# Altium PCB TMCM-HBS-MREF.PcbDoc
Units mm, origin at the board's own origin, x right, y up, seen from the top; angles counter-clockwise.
Board outline 55 x 85 mm, 4 copper layers (Top Layer, Mid1, Mid2, Bottom Layer), stack 1.546 mm thick; 61 components, 40 nets, 208 pads, 113 vias.
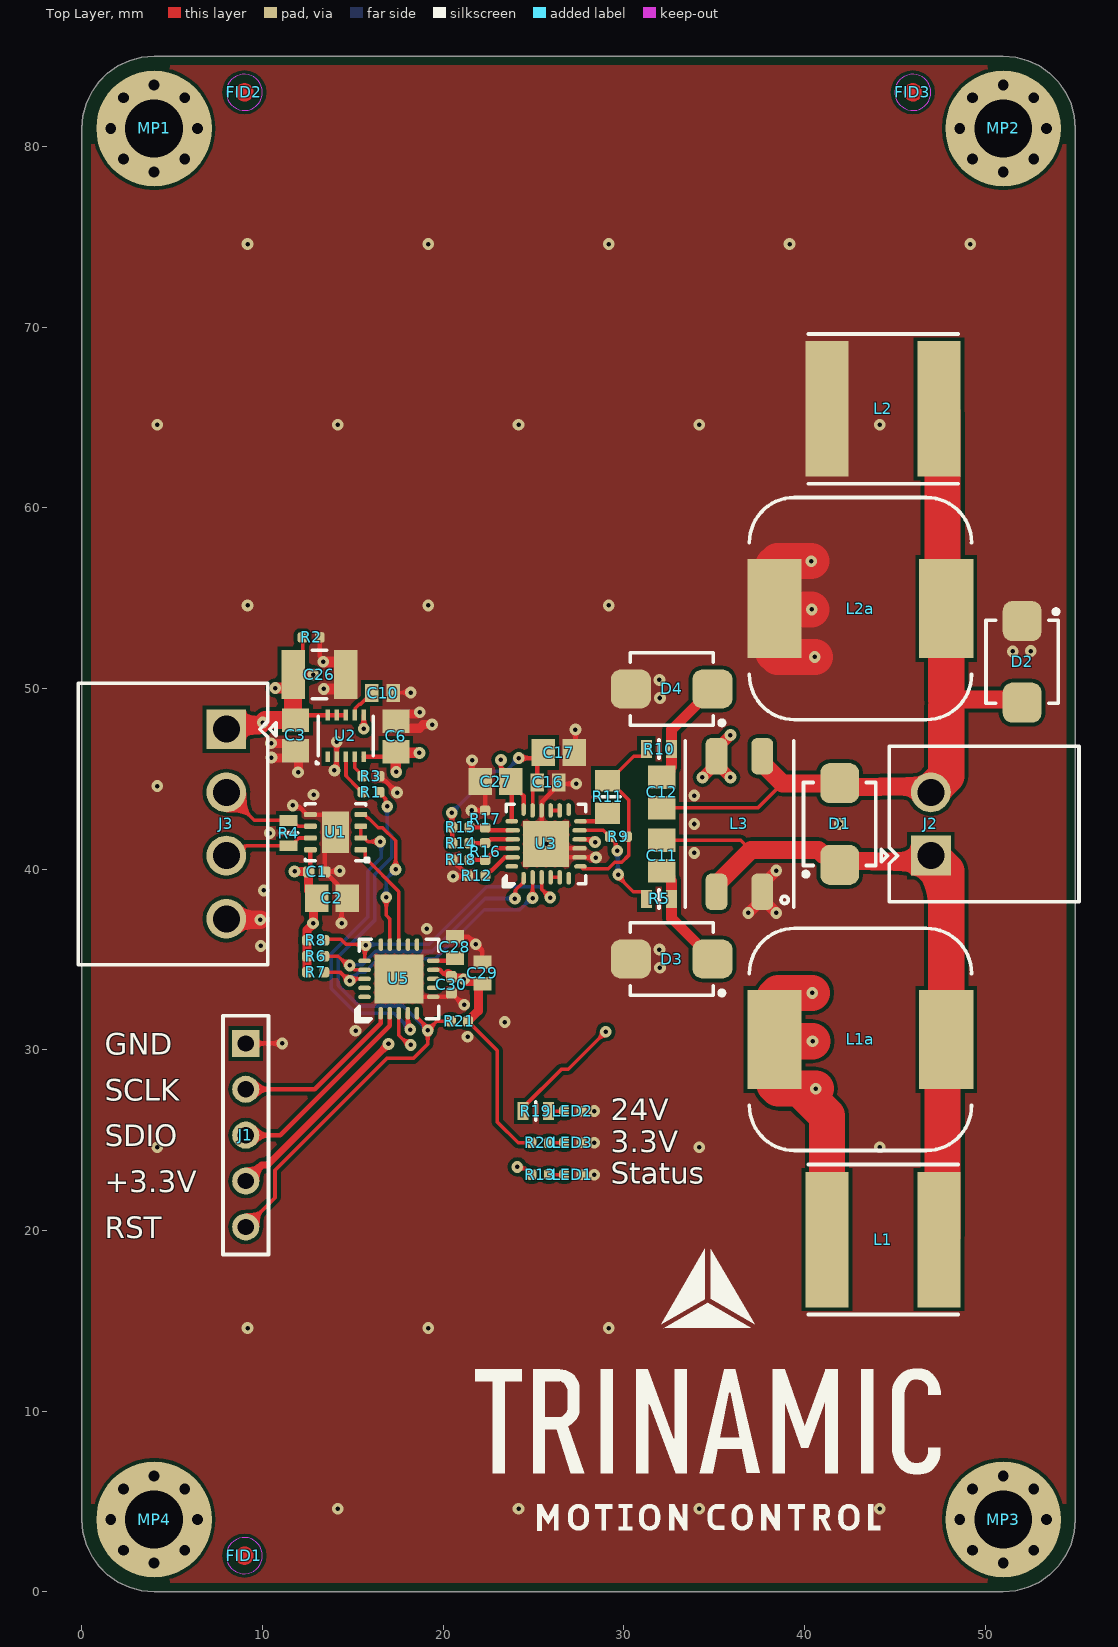
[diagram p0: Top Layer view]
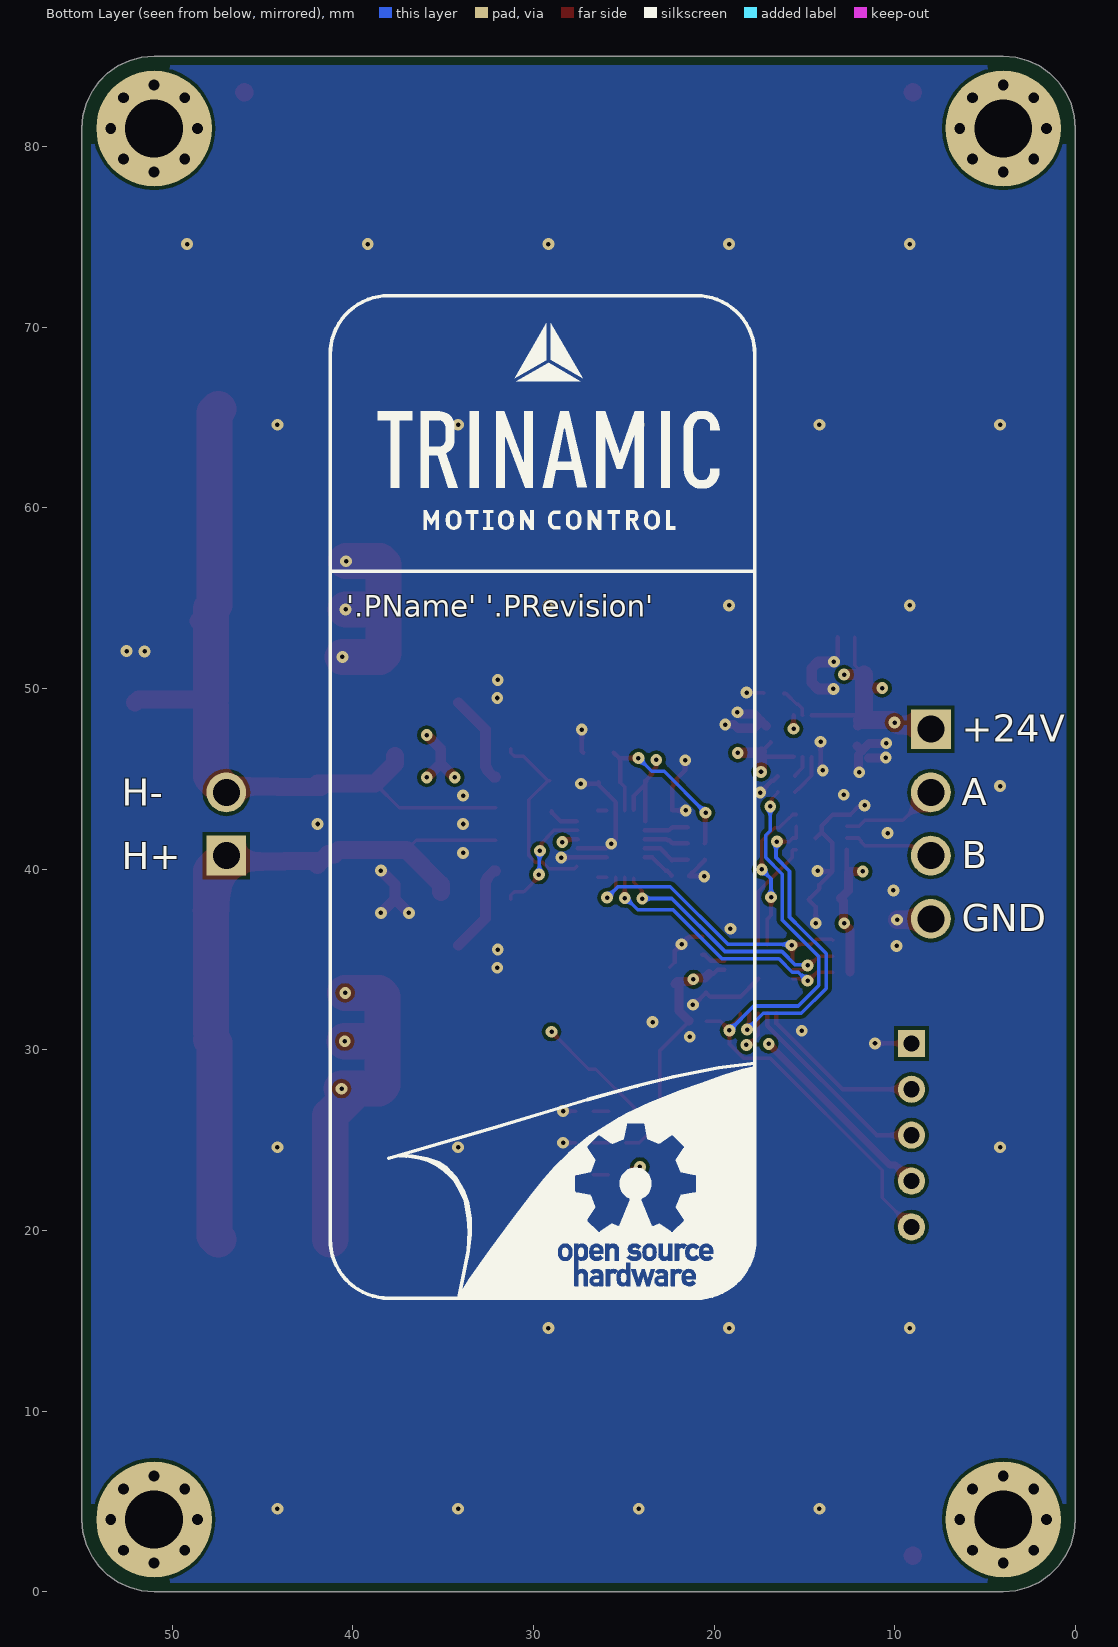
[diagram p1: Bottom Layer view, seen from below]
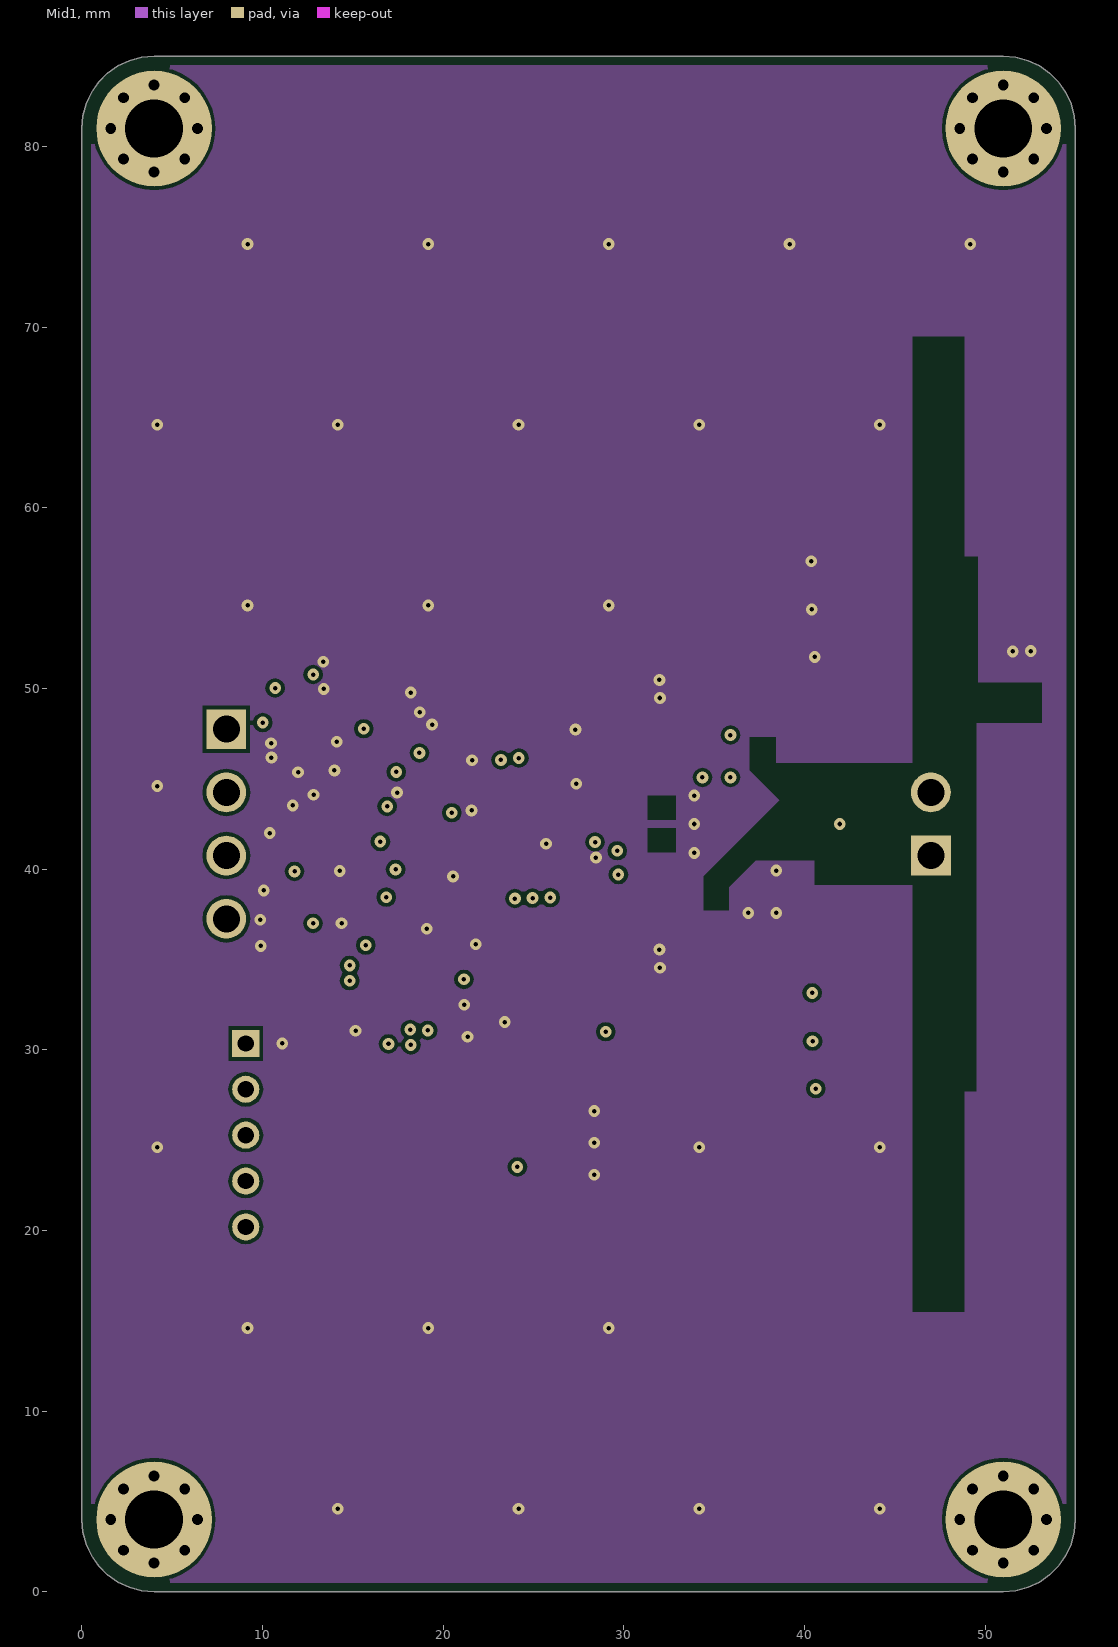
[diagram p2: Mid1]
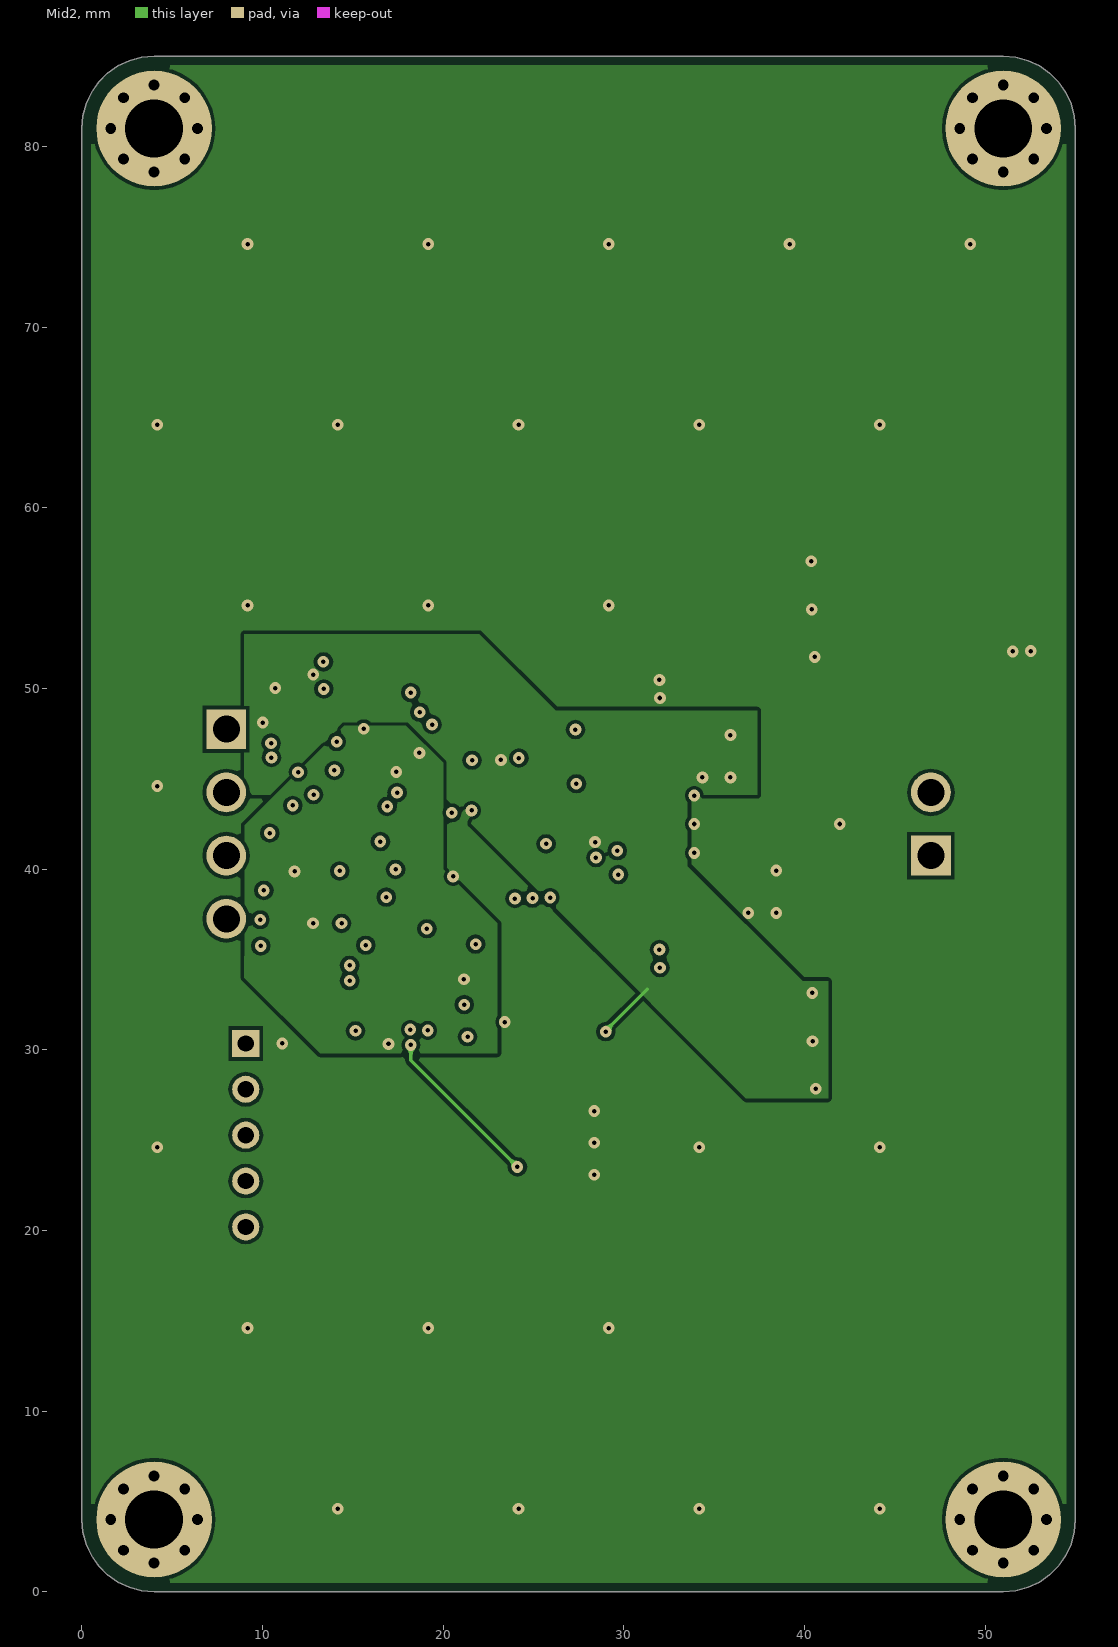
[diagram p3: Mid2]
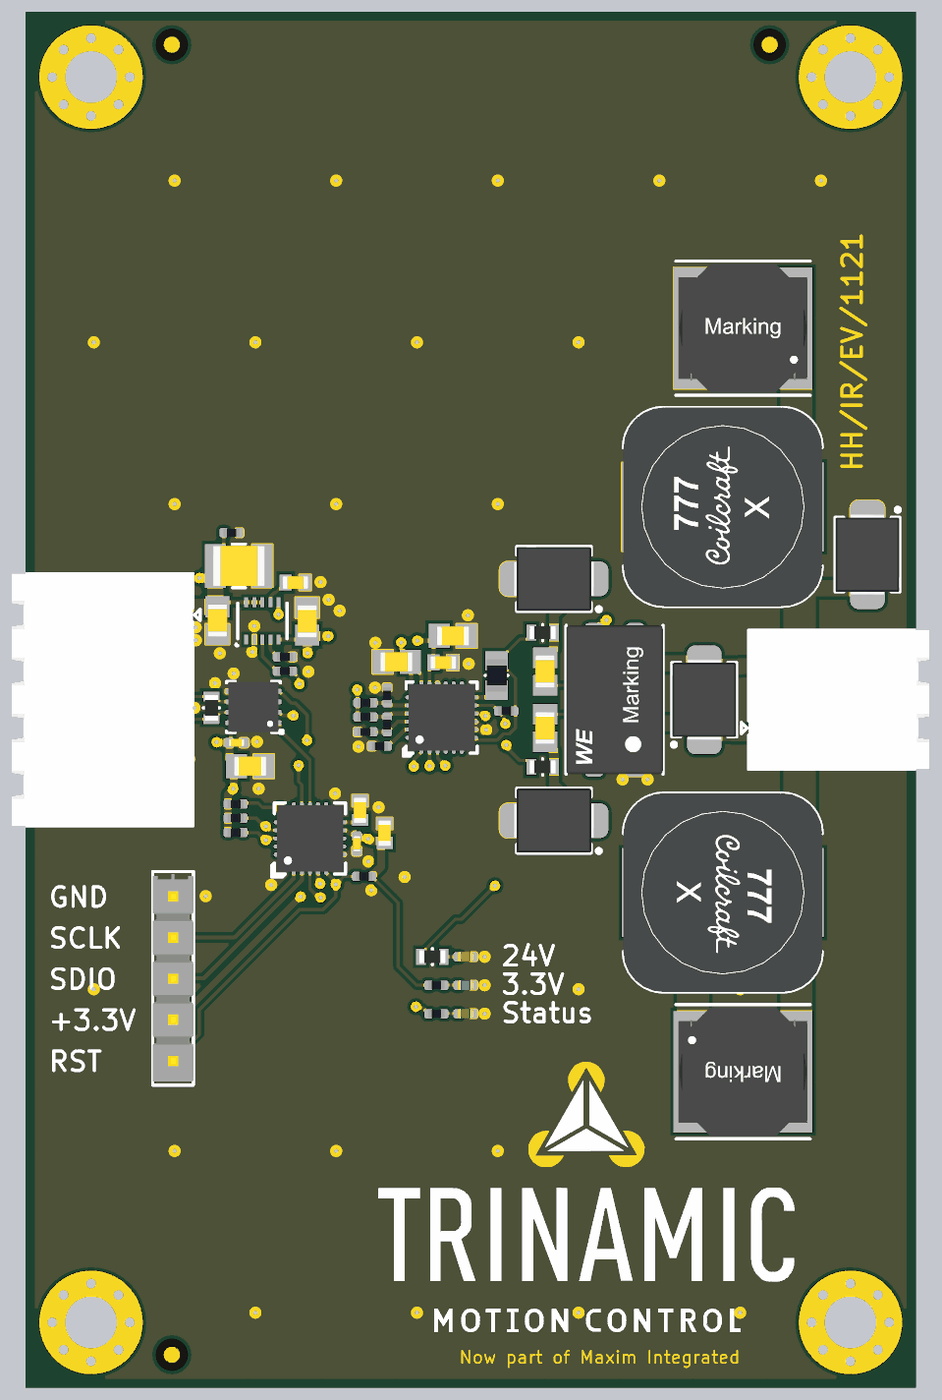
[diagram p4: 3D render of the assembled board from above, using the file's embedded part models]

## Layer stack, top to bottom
Top Solder: solder mask 0.01, Solder Resist, Dk 3.5
Top Layer: signal copper 0.018
Dielectric1: prepreg 0.18, FR-4, Dk 4.8
Mid1: signal copper 0.035
Dielectric2: core 1.08, FR-4, Dk 4.8
Mid2: signal copper 0.035
Dielectric3: prepreg 0.18, FR-4, Dk 4.8
Bottom Layer: signal copper 0.018
Bottom Solder: solder mask 0.01, Solder Resist, Dk 3.5

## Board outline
51,0 51.695,0.061 52.368,0.241 53,0.536 53.571,0.936 54.064,1.429 54.464,2 54.759,2.632 54.939,3.305 55,4 55,81 54.939,81.695 54.759,82.368 54.464,83 54.064,83.571 53.571,84.064 53,84.464 52.368,84.759 51.695,84.939 51,85 4,85 3.305,84.939 2.632,84.759 2,84.464 1.429,84.064 0.936,83.571 0.536,83 0.241,82.368 0.061,81.695 0,81 0,4 0.061,3.305 0.241,2.632 0.536,2 0.936,1.429 1.429,0.936 2,0.536 2.632,0.241 3.305,0.061 4,0

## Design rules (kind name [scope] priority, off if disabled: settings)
BoardOutlineClearance [OnCopper] p1: gap=0.5 ignorepadtopadclearanceinfootprint=FALSE
Clearance Clearance_Nonplated [IsPad and OnMultiLayer and not PadIsPlated] p1: gap=0.3 ignorepadtopadclearanceinfootprint=FALSE
Clearance [All] p2: gap=0.2 ignorepadtopadclearanceinfootprint=FALSE except(0.15: SMDPad-SMDPad)
ComponentClearance [All] p1: gap=0 collisioncheckmode=3 verticalgap=0 showdistances=TRUE
HoleSize [All] p1: absolutevalues=TRUE maxlimit=4 minlimit=0.25 maxpercent=80.000 minpercent=20.000
HoleToHoleClearance [All] p1: gap=0.3 allowstackedmicrovias=TRUE
MinimumAnnularRing [All] p1: minimumring=0.175
MinimumSolderMaskSliver [All] p1: minsoldermaskwidth=0.07
NetAntennae [All] p1: netantennaetolerance=0.2
PlaneClearance [All] p1: clearance=0.3
PlaneConnect [All] p1: planeconnectstyle=Direct reliefexpansion=0.3 reliefentries=4 reliefconductorwidth=0.2 reliefairgap=0.3
PolygonConnect [All] p1: thpad.connectstyle=NoConnect thpad.reliefconductorwidth=0.254 thpad.reliefentries=4 thpad.polygonreliefangle="90 Angle" thpad.airgapwidth=0.2 smdpad.connectstyle=Direct smdpad.reliefconductorwidth=0.254 smdpad.reliefentries=4 smdpad.polygonreliefangle="90 Angle" smdpad.airgapwidth=0.2 via.connectstyle=Direct via.reliefconductorwidth=0.254 via.reliefentries=4 via.polygonreliefangle="90 Angle" via.airgapwidth=0.2
RoutingCorners [All] p1: cornerstyle=45-Degree minsetback=0.2 maxsetback=2
RoutingVias [All] p1: holewidth=0.3 width=0.7 viastyle="Through Hole" minholewidth=0.3 minwidth=0.7 maxholewidth=0.6 maxwidth=1 useviatemplates=TRUE viatemplateguid#1={D7C2D780-1F83-44EE-A5DC-830EE216944E} viatemplatename#1=0.25x0.65-1thru4
SilkToSilkClearance [All] p1: silktosilkclearance=0.2
SilkToSolderMaskClearance [IsPad] p1: minsilkscreentomaskgap=0.2 clearancetoexposedcopper=TRUE
SolderMaskExpansion SolderMaskExpansionVia [IsVia] p1: expansion=0.1 istentingtop=FALSE soldermaskfromhole=TRUE
SolderMaskExpansion [All] p2: expansion=0.05 istentingtop=FALSE
Width [All] p1: maxlimit=2 minlimit=0.2 preferedwidth=0.2
20 further rules are at their usual default settings.

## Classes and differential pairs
component class MREF-RS485: C1 C2 J3 R4 U1
component class MREF-PSU: C3 C6 C10 R1 R3 U2
component class MREF-MCU: C28 C29 C30 J1 LED1 LED2 LED3 MP1 MP2 MP3 MP4 R13 R19 R20 R21 U5
component class MREF-HBS: C11 C12 C16 C17 C26 C27 D1 D2 D3 D4 J2 L1 L1a L2 L2a L3 R2 R5 R6 R7 R8 R9 R10 R11 R12 R14 R15 R16 R17 R18 U3

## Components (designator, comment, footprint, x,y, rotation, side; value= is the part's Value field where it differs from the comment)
C1 "CAPC" CAPC1005N 13.01,39.845 r180 top value=100n
C2 "CAPC" CAPC2012N 13.845,38.39 r180 top value=10u
C3 "CAPC" CAPC2012N 11.825,47.4 r90 top value=1u
C6 "CAPC" CAPC2012N 17.38,47.35 r270 top value=10u
C10 "CAPC" CAPC1608N 16.65,49.75 r180 top value=1u
C11 "CAPC" CAPC2012N 32.1,40.75 r270 top value=2.2u
C12 "CAPC" CAPC2012N 32.1,44.25 r90 top value=2.2u
C16 "CAPC" CAPC1608N 25.8,44.8 r180 top value=1u
C17 "CAPC" CAPC2012N 26.4,46.45 r180 top value=10u
C26 "CAPC" CAPC3225N 13.15,50.775 r180 top value=10u
C27 "CAPC" CAPC2012N 22.9,44.85 r180 top value=1u
C28 "CAPC" CAPC1608N 20.65,35.665 r270 top value=1u
C29 "CAPC" CAPC1608N 22.175,34.25 r270 top value=1u
C30 "CAPC" CAPC1005N 20.45,33.6 r90 top value=100n
D1 "TVS" DIOM4336X25N 41.95,42.5 r90 top value=24V,600W
D2 "TVS-SYM" DIOM4336X25N 52.05,51.475 r270 top value="6.8V,600W, Bidir"
D3 "TVS" DIOM4336X25N 32.65,35.025 r180 top value=6.8V,600W
D4 "TVS" DIOM4336X25N 32.65,49.975 r180 top value=6.8V,600W
FID1 "Comment" FID10X20 9,2 r0 top
FID2 "Comment" FID10X20 9,83 r0 top
FID3 "Comment" FID10X20 46,83 r0 top
J1 "HDR1x5" SAMTEC_TSW-105-07-G-S 9.075,25.275 r270 top value=1x5
J2 "HDR1x2A" PT11302HBBN 47,42.5 r270 top value="2 pin, 3.5mm"
J3 "HDR1x4A" PT11304HBBN 8,42.5 r90 top value="4 pin, 3.5mm"
L1 "INDM" WE-LQS_8065 44.35,19.5 r180 top value=10m
L1a "INDM" MSS1210 43.1,30.575 r180 top value=10m
L2 "INDM" WE-LQS_8065 44.35,65.475 r0 top value=10m
L2a "INDM" MSS1210 43.1,54.425 r0 top value=10m
L3 "IND_COM_MODE2" WE-SL2 36.4,42.5 r0 top value="10m, 350mA"
LED1 "DIO-LED" LED1005-GREEN 27.175,23.09 r180 top value=Green
LED2 "DIO-LED" LED1005-RED 27.175,26.61 r180 top value=Red
LED3 "DIO-LED" LED1005-BLUE 27.175,24.85 r180 top value=Blue
MP1 "MTG" MTG3,2_6,4-VIA 4,81 r0 top value="3.2x6.4 VIA"
MP2 "MTG" MTG3,2_6,4-VIA 51,81 r0 top value="3.2x6.4 VIA"
MP3 "MTG" MTG3,2_6,4-VIA 51,4 r0 top value="3.2x6.4 VIA"
MP4 "MTG" MTG3,2_6,4-VIA 4,4 r0 top value="3.2x6.4 VIA"
R1 "RESC" RESC1005N 16,44.27 r180 top value=0
R2 "RESC" RESC1005N 12.695,52.825 r0 top value=100k
R3 "RESC" RESC1005N 16,45.15 r0 top value=0
R4 "RESC" RESC1608N 11.45,42 r90 top value=120
R5 "RESC" RESC1608N 31.95,38.35 r180 top value=4.7
R6 "RESC" RESC1005N 12.95,35.18 r0 top value=2.7k
R7 "RESC" RESC1005N 12.95,34.3 r0 top value=20k
R8 "RESC" RESC1005N 12.95,36.06 r0 top value=100k
R9 "RESC" RESC1005N 29.7,41.8 r180 top value=1k
R10 "RESC" RESC1608N 31.95,46.65 r180 top value=4.7
R11 "RESC" RESC2012N 29.1,44 r90 top value=82
R12 "RESC" RESC1005N 21.865,39.635 r0 top value=62k
R13 "RESC" RESC1005N 25.375,23.09 r0 top value=300
R14 "RESC" RESC1005N 20.985,41.435 r180 top value=27k
R15 "RESC" RESC1005N 20.985,42.315 r0 top value=100k
R16 "RESC" RESC1005N 22.325,40.975 r90 top value=4.3k
R17 "RESC" RESC1005N 22.325,42.775 r90 top value=DNP
R18 "RESC" RESC1005N 20.985,40.515 r0 top value=20k
R19 "RESC" RESC1608N 25.125,26.61 r0 top value=10k
R20 "RESC" RESC1005N 25.375,24.85 r0 top value=100
R21 "RESC" RESC1005N 20.9,31.575 r180 top value=20k
U1 "RS485-9" SON65P300X80_HS-9N 14.05,42.05 r180 top value=RS-485
U2 "MAXM1506X" PSON50P260X165-10N-MFG 14.605,47.375 r90 top value="3.3V, 300mA buck PSU module"
U3 "MAX22088" QFN50P400X400X80_HS-25N 25.7,41.4 r90 top value="Home Bus System transceiver"
U5 "MAX32660GTP+" QFN50P400X400X80_HS-21N 17.55,33.925 r90 top value="ULP M4F MCU"

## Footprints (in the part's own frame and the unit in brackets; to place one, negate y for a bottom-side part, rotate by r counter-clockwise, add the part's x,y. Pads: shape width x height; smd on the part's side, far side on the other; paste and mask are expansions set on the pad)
CAPC1005N [mm] "Chip capacitor. C1005 (0402)."
  rrect49% 0.63x0.61 smd: 1(-0.45,0) 2(0.45,0)
  body extent -0.5,-0.25 0.5,0.25, height 0.55
CAPC1608N [mm] "Chip capacitor. C1608 (0603)."
  rect 0.75x1 smd: 1(-0.6,0) 2(0.6,0)
  body extent -0.8,-0.4 0.8,0.4, height 0.92
CAPC2012N [mm] "Chip capacitor. C2012 (0805)."
  rect 1.3x1.5 smd: 1(-0.85,0) 2(0.85,0)
  body extent -1,-0.6 1,0.6, height 1.45
CAPC3225N [mm] "Chip capacitor. C3225 (1210)."
  rect 1.3x2.7 smd: 1(-1.45,0) 2(1.45,0)
  silkscreen extent -0.4,-1.35 0.4,1.35, body extent -1.6,-1.25 1.6,1.25, height 2.79
DIOM4336X25N [mm] "Molded Diode, 2-Leads, Body 4.32x3.63mm, IPC Medium Density, SMB, DO-214AA"
  rrect50% 2.22x2.15 smd: 1(-2.26,0) 2(2.26,0)
  silkscreen extent -2.9,-2 2.3,2, body extent -2.52,-1.97 2.52,1.97, height 2.45
FID10X20 [mm] "Fiducial"
  Top Layer circle w0.5: c0,0 r0.25
  Top Layer region: 0,-0.5 -0.191,-0.462 -0.354,-0.354 -0.462,-0.191 -0.5,0 -0.5,0 -0.462,0.191 -0.354,0.354 -0.191,0.462 0,0.5 0,0.5 0.191,0.462 0.354,0.354 0.462,0.191 0.5,0 0.5,0 0.462,-0.191 0.354,-0.354 0.191,-0.462 0,-0.5
  Top Layer keep-out circle w0.01: c0,0 r1
LED1005-BLUE [mm] "SMD LED 1005 (0402)."
  rrect51% 0.55x0.58 smd: 1(-0.475,0) 2(0.475,0)
  body extent -0.5,-0.3 0.5,0.3, height 0.2
LED1005-GREEN [mm] "SMD LED 1005 (0402)."
  rrect51% 0.55x0.58 smd: 1(-0.475,0) 2(0.475,0)
  body extent -0.5,-0.3 0.5,0.3, height 0.2
LED1005-RED [mm] "SMD LED 1005 (0402)."
  rrect51% 0.55x0.58 smd: 1(-0.475,0) 2(0.475,0)
  body extent -0.5,-0.3 0.5,0.3, height 0.2
MSS1210 [mm] "Coilcraft power inductor, body 12x12x10mm"
  rect 3x5.5 smd: 1(-4.75,0) 2(4.75,0)
  silkscreen extent -6.15,-6.15 6.15,6.15, body extent -6.15,-6.15 6.15,6.15, height 10.26
MTG3,2_6,4-VIA [mm] "3,2mm ID/6.4mm OD mounting hole, reinforced with vias"
  round 1 hole 0.6: 1(-2.4,0) 1(-1.697,-1.697) 1(-1.697,1.697) 1(0,-2.4) 1(0,2.4) 1(1.697,-1.697) 1(1.697,1.697) 1(2.4,0)
  round 6.4 hole 3.2 paste-3.3: 1(0,0)
PSON50P260X165-10N-MFG [mm] "MAX102A3+2, PSON, 10-Leads, Body 3,00x2,60mm, Pitch 0,50mm, IPC Medium Density"
  rect 0.6x0.25 smd: 1(-1.15,1) 2(-1.15,0.5) 3(-1.15,0) 4(-1.15,-0.5) 5(-1.15,-1) 6(1.15,-1) 7(1.15,-0.5) 8(1.15,0) 9(1.15,0.5) 10(1.15,1)
  silkscreen extent -1.53,-1.52 1.1,1.63, body extent -1.32,-1.52 1.33,1.53, height 1.65
PT11302HBBN [mm] "3.50 mm centerline, PT113xxHBBN Typ 182, pin header"
  rect 2.2x2.2 hole 1.5: 1(1.75,0)
  round 2.2 hole 1.5: 2(-1.75,0)
  silkscreen extent -4.3,-2.75 4.3,8.2, body extent -4.3,-2.3 4.3,8.9, height 8.7
PT11304HBBN [mm] "3.50 mm centerline, PT113xxHBBN Typ 182, pin header"
  rect 2.2x2.2 hole 1.5: 1(5.25,0)
  round 2.2 hole 1.5: 2(1.75,0) 3(-1.75,0) 4(-5.25,0)
  silkscreen extent -7.8,-2.75 7.8,8.2, body extent -7.8,-2.3 7.8,8.9, height 8.7
QFN50P400X400X80_HS-21N [mm] "QFN, 20-Leads, Body 4,00x4,00mm, Pitch 0,50mm, Thermal Pad 2,70x2,70mm, IPC Medium Density"
  oval 0.7x0.25 smd: 1(-1.9,1) 2(-1.9,0.5) 3(-1.9,0) 4(-1.9,-0.5) 5(-1.9,-1) 11(1.9,-1) 12(1.9,-0.5) 13(1.9,0) 14(1.9,0.5) 15(1.9,1)
  oval 0.25x0.7 smd: 6(-1,-1.9) 7(-0.5,-1.9) 8(0,-1.9) 9(0.5,-1.9) 10(1,-1.9) 16(1,1.9) 17(0.5,1.9) 18(0,1.9) 19(-0.5,1.9) 20(-1,1.9)
  rect 2.7x2.7 smd paste-2: 21(0,0)
  silkscreen extent -2.37,-2.2 2.2,2.37, body extent -2.05,-2.05 2.05,2.05, height 0.8
QFN50P400X400X80_HS-25N [mm] "Maxim T2444-4C, QFN, 24-Leads, Body 4,00x4,00mm, Pitch 0,50mm, Thermal Pad 2,54x2,54mm, IPC Medium Density"
  oval 0.7x0.25 smd: 1(-1.9,1.25) 6(-1.9,-1.25) 13(1.9,-1.25) 18(1.9,1.25)
  oval 0.8x0.25 smd: 2(-1.85,0.75) 3(-1.85,0.25) 4(-1.85,-0.25) 5(-1.85,-0.75) 14(1.85,-0.75) 15(1.85,-0.25) 16(1.85,0.25) 17(1.85,0.75)
  oval 0.25x0.7 smd: 7(-1.25,-1.9) 12(1.25,-1.9) 19(1.25,1.9) 24(-1.25,1.9)
  oval 0.25x0.8 smd: 8(-0.75,-1.85) 9(-0.25,-1.85) 10(0.25,-1.85) 11(0.75,-1.85) 20(0.75,1.85) 21(0.25,1.85) 22(-0.25,1.85) 23(-0.75,1.85)
  rect 2.54x2.54 smd paste-2: 25(0,0)
  silkscreen extent -2.37,-2.2 2.2,2.37, body extent -2.05,-2.05 2.05,2.05, height 0.8
RESC1005N [mm] "Chip resistor C1005 (0402)."
  rrect51% 0.55x0.58 smd: 1(-0.475,0) 2(0.475,0)
  body extent -0.5,-0.25 0.5,0.25, height 0.33
RESC1608N [mm] "Chip resistor C1608 (0603)."
  rect 0.6x1 smd: 1(-0.7,0) 2(0.7,0)
  silkscreen extent 0,-0.5 0,0.5, body extent -0.8,-0.4 0.8,0.4, height 0.45
RESC2012N [mm] "Chip resistor C2012 (0805)."
  rect 1.2x1.4 smd: 1(-0.9,0) 2(0.9,0)
  silkscreen extent 0,-0.7 0,0.7, body extent -1,-0.63 1,0.62, height 0.58
SAMTEC_TSW-105-07-G-S [mm] "Pinheader male, square pin, 2.54 pitch, height 2.5+6.1"
  rect 1.5x1.5 hole 0.9: 1(-5.08,0)
  round 1.5 hole 0.9: 2(-2.54,0) 3(0,0) 4(2.54,0) 5(5.08,0)
  silkscreen extent -6.6,-1.26 6.6,1.26, body extent -6.45,-1.27 6.37,1.27, height 8.38
SON65P300X80_HS-9N [mm] "SON, 8-Leads, Body 3.00x3.00mm, Pitch 0.65mm, Thermal Pad 2.30x1.50mm, IPC Medium Density"
  rrect50% 0.7x0.3 smd: 1(-1.395,0.975) 2(-1.395,0.325) 3(-1.395,-0.325) 4(-1.395,-0.975) 5(1.395,-0.975) 6(1.395,-0.325) 7(1.395,0.325) 8(1.395,0.975)
  rect 1.5x2.3 smd paste-1: 9(0,0)
  silkscreen extent -1.82,-1.58 1.67,1.62, body extent -1.55,-1.55 1.55,1.55, height 0.8
WE-LQS_8065 [mm] "SMD Power Inductor, 2-Leads, body 8.3x8.3mm"
  rect 2.4x7.5 smd: 1(-3.1,0) 2(3.1,0)
  silkscreen extent -4.15,-4.15 4.15,4.15, body extent -4,-4 4,4, height 6.52
WE-SL2 [mm] "WE-SL2 Series - Common mode choke"
  rrect50% 1.2x2 smd: 1(-1.27,-3.75) 2(1.27,-3.75) 3(1.27,3.75) 4(-1.27,3.75)
  silkscreen extent -3,-4.6 3,4.6, body extent -3,-4.6 3,4.6, height 5

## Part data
C1 C30: library part 20203, "Ceramic chip capacitor", Manufacturer=Any, Package="0402 (1005 metric) chip capacitor", Part Number="100n, 50V, X7R, 0402 (1005 metric) chip capacitor", Voltage=50V
C2 C6 C17: library part 20166, "Ceramic chip capacitor", Manufacturer=Any, Package="0805 (2012 metric) chip capacitor", Part Number="10u, 10V, X7R, 0805 (2012 metric) chip capacitor", Voltage=10V
C3 C27: library part 20079, "Ceramic chip capacitor", Manufacturer=Any, Package="0805 (2012 metric) chip capacitor", Part Number="1u, 50V, X5R, 0805 (2012 metric) chip capacitor", Voltage=50V
C10 C16 C28 C29: library part 20005, "Ceramic chip capacitor", Manufacturer=Any, Package="0603 (1608 metric) chip capacitor", Part Number="1u, 16V, X5R, 0603 (1608 metric) chip capacitor", Voltage=16V
C11 C12: library part 20202, "Ceramic chip capacitor", Manufacturer=Any, Package="0805 (2012 metric) chip capacitor", Part Number="2.2u, 50V, X7R, 0805 (2012 metric) chip capacitor", Voltage=50V
C26: library part 30010, "Ceramic chip capacitor", Manufacturer=Samsung, Package="1210 (3225 metric) chip capacitor", Part Number=CL32B106KBJNNN, Voltage=50V
D1: library part 51483, "TVS, Pin1 Cathode", Manufacturer=Littelfuse, Part Number=SMBJ24A
D2: library part 51484, "Transient Voltage Suppression (TVS) Diode", Manufacturer=Littelfuse, Part Number=P6SMB6.8CA
D3 D4: library part 51475, "TVS, Pin1 Cathode", Manufacturer=Littelfuse, Part Number=P6SMB6.8A
J1: library part 50584, "1X5 pin connector", Manufacturer=Samtec, Part Number=TSW-105-07-G-S
J2: library part 51518, "1X2 pin connector", Manufacturer="Metz Connect", Part Number=31182102
J3: library part 50511, "1X4 pin connector", Manufacturer="Metz Connect", Part Number=31182104
L1 L2: library part 60123, "Molded inductor", Current=0.2A, Manufacturer=Wurth, Part Number=74404086103, Tolerance=20%
L1a L2a: library part 60125, "Molded inductor", Current=0.24A, Manufacturer=Coilcraft, Part Number=MSS1210-106KE, Tolerance=10%
L3: library part 51520, "Common mode inductor, pins 1 and 2 dot", Manufacturer=Wurth, Part Number=744220103
LED1: library part 51636, "LED, pin 1 cathode", Manufacturer=ROHM, Part Number=SML-P13PTT86R
LED2: library part 51637, "LED, pin 1 cathode", Manufacturer=ROHM, Part Number=SML-P12VTT86R
LED3: library part 51638, "LED, pin 1 cathode", Manufacturer=ROHM, Part Number=SMLP13BC8TT86
MP1 MP2 MP3 MP4: library part 50193, "Mounting hole", Part Number="M3 mounting hole"
R1 R3: library part 10052, "Chip Resistor", Manufacturer=Any, Package="0402 (1005 metric) chip resistor", Part Number="0, -, -, 0402 (1005 metric) chip resistor", Power=-
R2 R8 R15: library part 10010, "Chip Resistor", Manufacturer=Any, Package="0402 (1005 metric) chip resistor", Part Number="100k, 1%, 62mW, 0402 (1005 metric) chip resistor", Power=62mW, Tolerance=1%
R4: library part 10047, "Chip Resistor", Manufacturer=Any, Package="0603 (1608 metric) chip resistor", Part Number="120, 1%, 100mW, 0603 (1608 metric) chip resistor", Power=100mW, Tolerance=1%
R5 R10: library part 10140, "Chip Resistor", Manufacturer=Any, Package="0603 (1608 metric) chip resistor", Part Number="4.7, 1%, 100mW, 0603 (1608 metric) chip resistor", Power=100mW, Tolerance=1%
R6: library part 10061, "Chip Resistor", Manufacturer=Any, Package="0402 (1005 metric) chip resistor", Part Number="2.7k, 1%, 62mW, 0402 (1005 metric) chip resistor", Power=62mW, Tolerance=1%
R7 R18 R21: library part 10083, "Chip Resistor", Manufacturer=Any, Package="0402 (1005 metric) chip resistor", Part Number="20k, 1%, 62mW, 0402 (1005 metric) chip resistor", Power=62mW, Tolerance=1%
R9: library part 10014, "Chip Resistor", Manufacturer=Any, Package="0402 (1005 metric) chip resistor", Part Number="1k, 1%, 62mW, 0402 (1005 metric) chip resistor", Power=62mW, Tolerance=1%
R11: library part 10446, "Chip Resistor", Manufacturer=Any, Package="0805 (2012 metric) chip resistor", Part Number="82, 0.1%, 125mW, 0805 (2012 metric) chip resistor", Power=125mW, Tolerance=0.1%
R12: library part 10447, "Chip Resistor", Manufacturer=Any, Package="0402 (1005 metric) chip resistor", Part Number="62k, 1%, 62mW, 0402 (1005 metric) chip resistor", Power=62mW, Tolerance=1%
R13: library part 10332, "Chip Resistor", Manufacturer=Any, Package="0402 (1005 metric) chip resistor", Part Number="300, 1%, 62mW, 0402 (1005 metric) chip resistor", Power=62mW, Tolerance=1%
R14: library part 10241, "Chip Resistor", Manufacturer=Any, Package="0402 (1005 metric) chip resistor", Part Number="27k, 1%, 62mW, 0402 (1005 metric) chip resistor", Power=62mW, Tolerance=1%
R16: library part 10448, "Chip Resistor", Manufacturer=Any, Package="0402 (1005 metric) chip resistor", Part Number="4.3k, 1%, 62mW, 0402 (1005 metric) chip resistor", Power=62mW, Tolerance=1%
R17: library part 40006, "Chip Resistor", Manufacturer=DNP, Package="0402 (1005 metric) chip resistor"
R19: library part 10028, "Chip Resistor", Manufacturer=Any, Package="0603 (1608 metric) chip resistor", Part Number="10k, 1%, 100mW, 0603 (1608 metric) chip resistor", Power=100mW, Tolerance=1%
R20: library part 10009, "Chip Resistor", Manufacturer=Any, Package="0402 (1005 metric) chip resistor", Part Number="100, 1%, 62mW, 0402 (1005 metric) chip resistor", Power=62mW, Tolerance=1%
U1: library part 51480, "Half-duplex RS-485/RS-422 Transceiver", Manufacturer="Maxim Integrated", Part Number=MAX14775EATA+
U2: library part 51519, Manufacturer="Maxim Integrated", Part Number=MAXM15065AMB+
U3: library part 51469, "Home Bus System (HBS) Compatible / Transceiver", Manufacturer="Maxim Integrated", Part Number=MAX22088GTG+
U5: library part 51470, Manufacturer="Maxim Integrated"

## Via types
v1: diameter 0.65, hole 0.25, Top Layer to Bottom Layer, 113 vias

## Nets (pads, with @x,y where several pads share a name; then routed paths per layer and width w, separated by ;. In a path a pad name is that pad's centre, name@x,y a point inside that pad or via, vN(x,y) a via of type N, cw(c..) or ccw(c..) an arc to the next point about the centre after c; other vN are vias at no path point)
+3.3V: C1.2 C2.2 C6.2 C29.2 C30.2 J1.4 R6.1 R7.1 R8.1 R20.1 R21.1 U1.8 U2.5 U2.6 U5.9 | length 38.6
  Top Layer w0.2: R21.1 21.382,31.575 R21.1@21.4,31.557 ; R21.1@21.4,31.6 R21.1@21.4,31.557 ; R20.1 24.15,24.85 23,26 23,29.959 21.609,31.35 21.607,31.35 R21.1@21.4,31.557
  Top Layer w0.25: C1.2@12.655,39.943 U1.8 ; U2.5 17.105,46.225 C6.2 C6.2@16.855,47.025 ; v1(15.605,47.77) U2.6 ; U5.9 19.811,34.425 20.011,34.225 C30.2@20.275,34.225
  Top Layer w0.4: J1.4 9.965,23.625 10.275,23.625 v1(16.976,30.326)
  Top Layer w0.5: v1(11.775,39.875) 11.79,39.86 12.545,39.86 C1.2 12.56,38.825 C2.2 12.829,38.224 12.829,37.029 v1(12.8,37) 12.8,36.959 12.475,36.634 R8.1 R6.1 R7.1 ; C30.2@20.275,34.225 C30.2 20.525,33.975 21.075,33.975 v1(21.15,33.9) 21.191,33.9 21.316,33.775 22.05,33.775 C29.2 22.071,33.65 21.946,33.525 21.946,32.161 21.4,31.615 R21.1@21.4,31.6
  Top Layer w0.6: C6.2@17.38,46.225 17.38,45.419 17.405,45.394 v1(17.405,45.38) ; C6.2 17.44,46.44 18.68,46.44 v1(18.69,46.431)
+5V: C16.2 C17.2 R14.2 R15.1 U3.17 | length 11.2
  Top Layer w0.2: U3.17 24.95,44.55 C16.2
  Top Layer w0.25: v1(20.475,43.125) 20.492,43.108 20.492,41.453 R14.2 ; v1(24.192,46.15) C17.2@25.25,46.15 ; C16.2 25.2,46.1 C17.2@25.25,46.15 ; C17.2 C17.2@25.25,46.15
  Bottom Layer w0.2: v1(20.475,43.125) 22.769,45.419 23.46,45.419 v1(24.192,46.15)
+24V: C3.2 C26.2 C27.1 J3.1 L1.2 L1a.2 L3.4 R2.1 R19.1 U2.8 U2.9 U2.10 U3.10 U3.18 U3.19 | length 54.7
  Top Layer w0.2: C26.2 12.22,51.295 R2.1 ; R19.1 24.425,26.81 26.547,28.932 26.932,28.932 v1(29,31)
  Top Layer w0.25: C3.2 12.1,48.525 U2.10 U2.9 U2.8 ; v1(23.202,46.044) 23.202,45.656 23.501,45.357 23.422,45.278 23.8,44.9 C27.1 23.8,44.8 C27.1@23.8,44.7 ; U3.19 C27.1@23.8,44.7 ; U3.18 24.45,44.05 C27.1@23.8,44.7 ; U3.10 28.152,41.65 28.3,41.502 v1(28.408,41.502)
  Top Layer w0.5: C3.2@11.775,48.2 C3.2@12.05,47.925
  Top Layer w0.6: v1@10.702,50.023 11.7,50.023 C26.2@11.805,50.023 ; C26.2 11.702,50.773 v1(12.805,50.773) ; v1(34.355,45.075) L3.4@35.13,45.85 ; v1(35.905,45.075) L3.4@35.13,45.85 ; v1(35.905,47.425) 35.13,46.65 L3.4 L3.4@35.13,45.85
  Top Layer w1: J3.1 8.225,47.975 9.875,47.975 v1(10.012,48.112) 10.15,48.25 C3.2@11.725,48.25 ; C26.2 11.7,50.023 11.7,48.275 C3.2@11.725,48.25 ; C3.2 C3.2@11.725,48.25
  Top Layer w2: 40,27.6 41.25,26.35 L1.2 ; v1(40.425,33.15) 38.55,33.15 38.35,32.95 L1a.2 ; v1(40.45,30.475) 38.45,30.475 L1a.2 ; v1(40.625,27.85) 38.55,27.85 38.35,28.05 L1a.2
  Mid2 w0.2: v1@29,31.051 31.306,33.357
  other v1: 10.7,50.025
\HPEN: R15.2 R17.1 U3.20 | length 2.5
  Top Layer w0.25: R15.2 21.467,42.308 22.317,42.308 R17.1 22.348,42.3 22.498,42.15 U3.20
\RST: J1.5 R1.1 R21.2 U5.5 | length 36.7
  Top Layer w0.2: J1.5 10.695,21.815 10.695,23.339 16.881,29.525 18.35,29.525 19.15,30.325 v1(19.15,31.075) ; R1.1 16.475,44.233 16.814,43.894 16.814,43.561 v1(16.9,43.475) ; U5.5 18.55,31.8 19.212,31.138 19.65,31.575 R21.2
  Bottom Layer w0.2: v1(16.9,43.475) 16.9,42.127 17.15,41.877 17.15,40.65 16.225,39.725 16.225,37.184 15.291,36.25 14.201,35.161 14.201,33.565 15.341,32.425 17.8,32.425 v1(19.15,31.075)
GND: C1.1 C2.1 C3.1 C6.1 C10.1 C16.1 C17.1 C26.1 C27.2 C28.1 C29.1 C30.1 D2.1 D3.2 D4.2 J1.1 J3.4 L2.1 L2a.1 L3.2 LED1.1 LED2.1 LED3.1 R2.2 R3.2 R12.1 R17.2 R18.1 U1.5 U1.9 U2.2 U3.8 U3.9 U3.16 U3.25 U5.6 U5.21 | length 72.8
  Top Layer w0.2: C10.1 17.275,49.775 v1(18.205,49.775) ; C29.1 C29.1@22.45,34.575 ; LED1.1 v1(28.36,23.09) ; LED3.1 v1(28.36,24.85) ; LED2.1 v1(28.36,26.61)
  Top Layer w0.25: J1.1 v1(11.095,30.355) ; v1(11.675,43.525) 11.752,43.448 12.032,43.448 12.455,43.025 U1.5 13.425,43.025 14.05,42.4 U1.9 ; R2.2 13.17,51.783 13.37,51.583 v1(13.37,51.475) ; v1@13.98,45.42 v1(13.98,45.463) 13.988,45.463 14.105,45.58 U2.2 v1(14.105,47.055) ; v1(14.273,39.902) 14.245,39.873 13.488,39.873 C1.1 ; v1(14.375,37) 14.375,37.91 14.775,38.31 C2.1 14.17,38.915 14.17,39.145 13.47,39.845 C1.1 ; U1.9@14.375,41.725 U1.9 ; R3.2 16.475,45.143 16.733,44.885 16.802,44.885 v1(17.45,44.237) ; U5.21 18.55,32.925 U5.6 20.222,32.925 20.447,33.15 C30.1 20.453,33.15 21.103,32.5 v1(21.171,32.5) ; R18.1 20.51,40.5 21.219,39.791 21.241,39.791 21.39,39.642 R12.1 21.372,39.618 20.568,39.618 v1(20.55,39.6) ; C28.1 21.385,36.265 v1(21.8,35.85) 22.175,35.475 C29.1 ; v1(21.575,43.25) R17.2 22.325,44.575 C27.2 ; v1(21.6,46.025) 21.6,45.475 22.225,44.85 C27.2@22.287,44.85 ; U3.25@25.45,41.65 U3.16 25.45,43.715 25.9,44.165 25.9,44.175 26.4,44.675 C16.1 26.475,44.725 v1(27.375,44.725) ; v1(25.7,41.4) 25.95,41.15 U3.9 ; U3.25@25.95,40.65 28.45,40.65 v1(28.459,40.641) ; C17.1 27.325,46.525 v1(27.325,47.725) ; C1.1 13.46,41.46 U1.9
  Top Layer w0.5: v1(10.475,46.975) 10.504,46.946 11.429,46.946 C3.1 C3.1@12.1,46.825 ; v1@10.525,46.15 C3.1@11.45,46.15 ; v1@12,45.4 C3.1@12,46.325 ; C6.1@17.105,47.925 C6.1 ; v1(18.707,48.684) 18.666,48.684 18.582,48.6 17.78,48.6 C6.1 ; v1(19.385,48.005) 18.895,48.005 18.69,47.8 17.78,47.8 C6.1
  Top Layer w0.6: v1(13.37,51.475) 14.25,51.475 14.6,51.125 C26.1 14.6,50.325 14.25,49.975 v1(13.395,49.975) ; v1(36.895,37.575) L3.2@37.67,38.35 ; v1(38.445,37.575) L3.2@37.67,38.35 ; v1(38.445,39.925) 37.67,39.15 L3.2 L3.2@37.67,38.35
  Top Layer w1: J3.4 8.05,37.2 v1(9.875,37.2)
  Top Layer w2: v1(40.375,57.05) 38.5,57.05 38.3,56.85 L2a.1@38.3,54.475 ; v1(40.4,54.375) 38.4,54.375 L2a.1@38.3,54.475 ; v1(40.575,51.75) 38.5,51.75 38.3,51.95 L2a.1@38.3,54.475
  other v1: 14.173,4.6 24.173,4.6 34.173,4.6 44.173,4.6 9.173,14.6 19.173,14.6 29.173,14.6 4.173,24.6 34.173,24.6 44.173,24.6 21.35,30.725 15.15,31.05 23.407,31.539 32,34.55 31.975,35.55 9.9,35.75 19.1,36.7 10.075,38.825 33.9,40.9 10.4,42 33.9,42.5 41.95,42.5 33.9,44.075 12.825,44.125 4.173,44.6 11.971,45.371 10.496,46.179 32,49.475 31.975,50.475 51.525,52.05 52.525,52.075 9.173,54.6 19.173,54.6 29.173,54.6 4.173,64.6 14.173,64.6 24.173,64.6 34.173,64.6 44.173,64.6 9.173,74.6 19.173,74.6 29.173,74.6 39.173,74.6 49.173,74.6
H+: C11.1 D1.1 J2.1 L1.1 L1a.1 L3.1 | length 40.2
  Top Layer w0.2: C11.1 36.48,41.6 37.03,41.05
  Top Layer w1: L3.1 35.13,39.15 37.03,41.05 40.789,41.05 41.012,40.827 41.378,40.827 41.95,40.255 D1.1 ; D1.1@41.755,40.45 43.742,40.45 43.775,40.417 46.822,40.417 J2.1@47,40.595
  Top Layer w2: J2.1 47.85,39.9 L1a.1@47.85,30.975 ; L1.1 47.65,19.7 47.65,30.375 L1a.1
H-: C12.1 D1.2 D2.2 J2.2 L2.2 L2a.2 L3.3 | length 44.6
  Top Layer w0.2: C12.1 37.429,43.4 38.775,44.745
  Top Layer w1: L3.3 37.67,45.85 38.775,44.745 41.95,44.745 41.755,44.55 44.167,44.55 44.2,44.582 46.822,44.582 J2.2@47,44.405 ; L2a.2@47.65,54.625 L2a.2 L2a.2@48.54,53.735 ; 47.85,49.4 51.865,49.4 D2.2
  Top Layer w2: J2.2 47,44.304 47.85,45.154 47.85,49 ; L2.2 47.65,65.275 L2a.2@47.65,54.625 ; 47.85,49.4 L2a.2
LED.Status: R13.1 U5.3 | length 12.3
  Top Layer w0.2: U5.3 17.55,30.813 18.091,30.272 v1(18.213,30.272) ; v1(24.109,23.52) 24.195,23.434 24.549,23.434 24.893,23.09 R13.1
  Mid2 w0.2: v1(18.213,30.272) 18.213,29.416 v1(24.109,23.52)
MTG1: MP1.1
MTG2: MP2.1
MTG3: MP3.1
MTG4: MP4.1
NetC10_2: C10.2 U2.7 | length 1.7
  Top Layer w0.2: U2.7 15.13,48.55 15.13,48.899 15.356,49.125 15.425,49.125 16.025,49.725 C10.2@16.15,49.725
NetC11_2: C11.2 D3.1 R5.1 | length 5
  Top Layer w0.6: C11.2 32.2,39.9 32.55,39.55 32.55,39.45 32.65,39.35 R5.1 32.65,37.285 D3.1@34.15,35.785
NetC12_2: C12.2 D4.1 R10.1 | length 5
  Top Layer w0.6: C12.2 32.2,45.1 32.55,45.45 32.55,45.55 32.65,45.65 R10.1 32.65,47.715 D4.1@34.15,49.215
NetC28_2: C28.2 U5.10 | length 1.3
  Top Layer w0.25: U5.10 20.2,34.925 20.525,35.25 C28.2@20.65,35.25
NetLED1_2: LED1.2 R13.2 | length 0.9
  Top Layer w0.2: R13.2 LED1.2
NetLED2_2: LED2.2 R19.2 | length 0.9
  Top Layer w0.2: R19.2 LED2.2
NetLED3_2: LED3.2 R20.2 | length 0.9
  Top Layer w0.2: R20.2 LED3.2
NetR1_2: R1.2 U2.3 | length 3.4
  Top Layer w0.2: 14.65,45.15 14.628,45.173 14.628,46.203 U2.3 14.605,45.163 15.333,44.435 15.36,44.435 R1.2
NetR3_1: R3.1 U2.4 | length 1.2
  Top Layer w0.2: U2.4 15.105,45.607 15.525,45.187 R3.1
NetR5_2: R5.2 R9.2 U3.11 | length 6.4
  Top Layer w0.2: U3.11 28.868,42.15 29.218,41.8 R9.2 29.225,41.763 29.553,41.436 29.553,41.102 v1(29.639,41.016) ; v1(29.7,39.7) 29.7,39.578 30.528,38.75 31.05,38.75 31.25,38.55 R5.2
  Bottom Layer w0.2: v1(29.639,41.016) 29.669,40.985 29.669,39.731 v1(29.7,39.7)
NetR9_1: R9.1 R10.2 R11.2 U3.7 | length 10.6
  Top Layer w0.2: U3.7 27.734,40.016 29.132,40.016 29.503,40.387 29.893,40.387 30.264,40.757 30.264,43.836 R11.2@29.2,44.9 ; R11.2 R11.2@29.2,44.9 ; R10.2 31.25,46.45 31.05,46.25 30.55,46.25 R11.2@29.2,44.9
NetR11_1: R11.1 U3.12 | length 1.6
  Top Layer w0.25: U3.12 28.5,42.65 28.975,43.125 R11.1@28.975,43.2
NetR12_2: R12.2 U3.23 | length 1.9
  Top Layer w0.25: R12.2 22.34,39.642 22.489,39.791 22.496,39.791 22.605,39.9 22.667,39.9 23.417,40.65 U3.23
NetR14_1: R14.1 R16.2 U3.21 | length 2.5
  Top Layer w0.25: R14.1 21.468,41.443 22.318,41.443 22.466,41.591 22.577,41.591 22.636,41.65 U3.21
NetR16_1: R16.1 R18.2 U3.22 | length 2.7
  Top Layer w0.25: R18.2 R16.1@22.355,40.515 ; R16.1 22.34,40.5 R16.1@22.355,40.515 ; U3.22 22.99,41.15 R16.1@22.355,40.515
NetU3_4: U3.4 U3.5 | length 0.5
  Top Layer w0.2: U3.4 U3.5
NetU3_14: U3.14 U3.15 | length 0.5
  Top Layer w0.2: U3.15 U3.14
RS-485-A: J3.2 R4.2 U1.6 | length 5.4
  Top Layer w0.2: J3.2 9.55,42.7 R4.2 11.65,42.7 11.975,42.375 U1.6
RS-485-B: J3.3 R4.1 U1.7 | length 5.1
  Top Layer w0.2: J3.3 8.541,40.75 9.091,41.3 11.65,41.3 11.85,41.5 11.85,41.57 12.005,41.725 U1.7
RST2: R8.2 U3.3 U5.16 | length 16.5
  Top Layer w0.2: R8.2 13.483,36.117 14.342,36.117 14.621,35.839 15.672,35.839 15.672,35.836 v1(15.716,35.792) ; U5.16 15.661,34.936 v1@15.661,35.829 ; U3.3 25.45,38.9 v1(25.925,38.425)
  Bottom Layer w0.2: v1(15.716,35.792) 15.763,35.839 19.236,35.839 22.422,39.025 25.325,39.025 v1(25.925,38.425)
SWDCLK: J1.2 U5.1 | length 9.5
  Top Layer w0.25: J1.2 12.89,27.815 16.55,31.475 U5.1
SWDIO: J1.3 U5.2 | length 11.2
  Top Layer w0.25: J1.3 10.986,25.275 17.05,31.339 U5.2
UART0_RX: R6.2 U3.1 U5.17 | length 14.5
  Top Layer w0.2: R6.2 14.201,35.18 14.707,34.673 v1(14.826,34.673) ; v1@14.827,34.675 15.077,34.425 U5.17 ; v1(23.975,38.375) 24,38.4 24,38.825 24.45,39.275 U3.1
  Bottom Layer w0.2: v1(14.826,34.673) 14.853,34.701 15.508,34.701 16.247,35.439 19.402,35.439 22.338,38.375 v1(23.975,38.375)
UART0_TX: R7.2 U3.2 U5.18 | length 15.7
  Top Layer w0.2: R7.2 13.44,34.285 14.316,34.285 14.657,33.943 v1@14.826,33.943 ; v1@14.826,33.824 v1@14.826,33.943 ; U5.18 15.632,33.943 v1@14.826,33.943 ; v1(24.95,38.4) U3.2
  Bottom Layer w0.2: v1(14.826,33.823) 14.86,33.823 15.337,34.301 15.674,34.301 16.413,35.039 19.568,35.039 22.278,37.75 24.234,37.75 24.884,38.4 v1(24.95,38.4)
UART1_RX: U1.1 U5.13 | length 6.2
  Top Layer w0.2: U1.1 15.635,41.075 15.685,41.025 15.685,40.625 17.55,38.76 U5.13
UART1_TX: U1.4 U5.14 | length 8.6
  Top Layer w0.2: U1.4 15.645,43.025 15.845,42.825 15.875,42.825 16.408,42.292 16.644,42.292 17.37,41.566 v1(17.37,39.986) ; v1(16.85,38.45) 16.85,37.442 17.05,37.242 U5.14
  Bottom Layer w0.2: v1(16.85,38.45) 16.85,39.466 v1(17.37,39.986)
UART1_TxEn: U1.2 U1.3 U5.4 | length 17.4
  Top Layer w0.2: U1.3 U1.2 15.645,41.725 15.695,41.675 15.845,41.525 v1(16.525,41.525)
  Top Layer w0.25: U5.4 18.05,31.251 v1(18.18,31.121)
  Bottom Layer w0.2: 15.124,36.65 13.801,35.326 13.801,33.399 15.175,32.025 17.276,32.025 v1(18.18,31.121) ; 15.125,36.65 15.825,37.35 15.825,39.891 16.575,40.641 16.575,41.475 v1(16.525,41.525)
pads on no net: U2.1 U3.6 U3.13 U3.24 U5.7 U5.8 U5.11 U5.12 U5.15 U5.19 U5.20

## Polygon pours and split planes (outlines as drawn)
GND on Mid2 "GND_L03_P004" (solid, remove dead copper, pour order 4): 0,0 55,0 55,85 0,85
+3.3V on Mid2 "+3.3V_L03_P000" (solid, remove dead copper, pour order 0): 9.022,42.422 14.538,47.938 17.94,47.938 20,45.878 20,40 23,37 23,29.8 13.2,29.8 9,34
+24V on Mid2 "+24V_L03_P001" (solid, remove dead copper, pour order 1): 9,44.125 9,53 22,53 26.225,48.775 37.38,48.775 37.38,44.125 33.525,44.125 33.525,40.175 39.9,33.8 41.306,33.8 41.306,27.315 36.76,27.315 19.95,44.125
GND on Mid1 "GND_L02_P003" (solid, remove dead copper, pour order 3): 0,0 55,0 55,85 0,85
GND on Bottom Layer "GND_L04_P005" (solid, remove dead copper, pour order 5): 0,0 55,0 55,85 0,85
GND on Top Layer "GND_L01_P002" (solid, remove dead copper, pour order 2): 0,85 55,85 55,0 0,0

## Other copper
Mid1:
  pour cut-out: 31.325,44.075 32.875,44.075 32.875,42.725 31.325,42.725
  pour cut-out: 31.325,42.275 32.875,42.275 32.875,40.925 31.325,40.925
  pour cut-out: 48.85,69.475 48.85,57.3 49.6,57.3 49.6,50.325 53.125,50.325 53.125,48.1 49.5,48.1 49.5,27.7 48.85,27.7 48.85,15.5 46,15.5 46,39.125 40.575,39.125 40.575,40.5 37.301,40.5 35.8,39 35.8,37.725 34.425,37.725 34.425,39.6 38.641,43.816 36.975,45.483 36.975,47.3 38.4,47.3 38.4,45.875 46,45.875 46,69.475

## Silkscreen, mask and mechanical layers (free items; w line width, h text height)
Top Overlay:
  drawing of 43 lines, arcs and shapes, not listed
  text "GND" at 1.275,29.73 h1.2
  text "SCLK" at 1.275,27.19 h1.2
  text "24V" at 29.275,26.095 h1.2
  text "SDIO" at 1.275,24.65 h1.2
  text "3.3V" at 29.275,24.335 h1.2
  text "Status" at 29.275,22.575 h1.2
  text "+3.3V" at 1.275,22.11 h1.2
  text "RST" at 1.275,19.57 h1.2
Bottom Overlay:
  drawing of 110 lines, arcs and shapes, not listed
  text "'.PName' '.PRevision'" at 40.35,53.975 h1.2
  text "+24V" at 6.3,47.05 h1.5
  text "A" at 6.3,43.55 h1.5
  text "H-" at 52.8,43.5 h1.5
  text "B" at 6.3,40.05 h1.5
  text "H+" at 52.8,40 h1.5
  text "GND" at 6.3,36.55 h1.5
Top Solder:
  region: 37.992,14.003 ccw(c36.158,15.317) 38.213,14.386 ccw(c35.738,14.898) 38.265,14.88 ccw(c36.382,14.299) 37.9,15.557 ccw(c37.049,14.528) 36.924,15.857
  region: 36.043,14.326 ccw(c38.051,15.362) 36.284,13.954 ccw(c37.965,15.843) 36.686,13.662 ccw(c37.124,15.583) 37.454,13.641 ccw(c36.937,15.005) 37.937,13.943 ccw(c37.076,14.775) 38.19,14.336
  region: 31.121,14.321 ccw(c33.177,15.252) 31.343,13.938 ccw(c33.023,15.826) 31.744,13.646 ccw(c32.183,15.567) 32.513,13.625 ccw(c32.048,14.875) 33.261,14.32
  region: 32.376,15.847 ccw(c32.269,13.591) 31.933,15.824 ccw(c32.728,13.425) 31.48,15.623 ccw(c32.923,14.283) 31.076,14.968 ccw(c32.517,14.734) 31.097,14.399 ccw(c32.248,14.729) 31.311,13.983
  region: 35.537,18.246 ccw(c33.636,19.467) 35.739,18.641 ccw(c33.264,19.152) 35.791,19.135 ccw(c33.909,18.554) 35.425,19.811 ccw(c34.503,18.681) 34.923,20.078 ccw(c34.633,18.917) 34.456,20.101
  region: 34.843,20.095 ccw(c34.622,17.85) 34.4,20.095 ccw(c35.195,17.697) 33.947,19.894 ccw(c35.392,18.553) 33.544,19.239 ccw(c34.859,19.017) 33.772,18.244
  text "HH/IR/EV/1121" at 51.675,56.525 h1.2 r90
  text "'.PName' '.PRevision'" at 53.75,56.5 h1.2 r90
  text "Now part of Maxim Integrated" at 26.722,1.484 h0.76
Bottom Solder:
  region: 28.514,69.688 cw(c29.909,70.583) 28.366,69.977 cw(c30.182,70.353) 28.328,70.34 cw(c29.709,69.914) 28.596,70.836 cw(c29.273,70.007) 28.965,71.032 cw(c29.178,70.179) 29.308,71.048
  region: 29.023,71.044 cw(c29.186,69.397) 29.348,71.044 cw(c28.765,69.285) 29.681,70.897 cw(c28.621,69.913) 29.977,70.416 cw(c29.011,70.253) 29.809,69.686
  region: 30.834,67.927 cw(c30.912,66.272) 31.159,67.911 cw(c30.575,66.15) 31.491,67.763 cw(c30.432,66.78) 31.787,67.282 cw(c30.73,67.111) 31.772,66.865 cw(c30.928,67.107) 31.615,66.56
  region: 31.754,66.808 cw(c30.246,67.491) 31.592,66.527 cw(c30.359,67.912) 31.297,66.313 cw(c30.975,67.722) 30.733,66.297 cw(c31.074,67.214) 30.184,66.807
  region: 26.713,66.574 cw(c28.059,67.539) 26.551,66.856 cw(c28.367,67.231) 26.513,67.218 cw(c27.894,66.792) 26.781,67.714 cw(c27.405,66.96) 27.497,67.934
  region: 28.143,66.812 cw(c26.67,67.572) 27.966,66.539 cw(c26.733,67.924) 27.672,66.325 cw(c27.35,67.734) 27.107,66.309 cw(c27.487,67.31) 26.753,66.53 cw(c27.385,67.141) 26.568,66.819
  text "Now part of Maxim Integrated" at 34.982,57.39 h0.56
Board:
  lines w0.1: 0,4 0,81 cw(c3.996,80.999) 3.996,84.995 ; 0.005,3.996 ccw(c4.001,3.996) 4,0 51,0 ; 4,85 51,85 cw(c50.999,81.004) 54.995,81.004 ; 51.004,0.005 ccw(c51.004,4.001) 55,4 55,81
  text "ALL THE FABRICATION REQUIREMENTS / ARE IN A SEPARATE PDF FILE." at -0.25,-7.1 h1.52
